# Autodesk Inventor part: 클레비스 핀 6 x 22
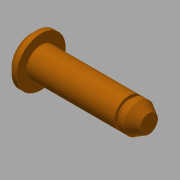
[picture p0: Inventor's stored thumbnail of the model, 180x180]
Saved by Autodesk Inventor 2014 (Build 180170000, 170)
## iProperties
IsCustomPart: 1
Created: 2017-08
Part Number: 클레비스 핀 6 x 22
Material: 강철
Description: 머리가 있는 클레비스 핀
Document SubType Name: Modeling
Standard: ISO 2341
Designer: mduedu
Standard Revision: Second edition 1986-11-01
Standards Organization: ISO
Language: ko-KR
Size Designation: B - 6 x 24
Categories: <MemberInstance><Categories><Category DisplayName="조임쇠" InternalName="e4da775c-781d-43d5-af7c-5136215cf5a6" Mnemonic="FSTN"><Category DisplayName="핀" InternalNa
Density: 7.85 g/cm^3
Appearance: Orange
Author: mduedu
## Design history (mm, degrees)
sketch "스케치1"
  geometry: L1 (-2, 0)-(-2, 5); L2 (-2, 5)-(0, 5); L3 (0, 5)-(0, 3); L4 (0, 3)-(22, 3); L5 (22, 3)-(22, 0); L6 (-2, 0)-(22, 0); L7 (-7, 0)-(28, 0) reference; L8 (0, -1.96)-(0, 6.16) reference; C1 r 0.8 at (18.8, 0)
  constraints: 12 end point, 3 parallel, 2 collinear, 2 perpendicular, 1 centre point, 1 point on line, 1 vertical
  dimensions: "d0" = 6 diameter of L4 L6 (= NND); "d1" = 10 diameter of L2 L6 (= KOD); "d2" = 2 distance of L1.end L2.end (= KOH); "d3" = 22 distance of L3.end L4.end (= NLG); "d5" = 3.2 distance from line of L5 C1.centre (= DIST); "d6" = 1.6 diameter of C1 (= BOR)
revolve "본체" stored, may be unused: angle "d4" = 90 deg
node "작업 평면4"
sketch "스케치2"
  geometry: C1 r 3 at (0, 0) reference; C2 r 2.425 at (0, 0); 1 further point
  constraints: 1 centre point, 1 coincident
  dimensions: "d33" = 4.85 diameter of C2
extrude "돌출2" cut sketch "스케치2" distance "d34" = 0.7; taper "d35" = 0 deg
body "Solid1"
chamfer "모따기1" distance "d9" = 1 (= PHH2); stored, may be unused: angle "d10" = 45 deg (= FAWI2), second distance "d16" = 1 (= PHH2)
chamfer "모따기2" distance "d11" = 2 (= PHH1); stored, may be unused: angle "d12" = 30 deg (= FAWI1), second distance "d17" = 2 (= PHH1)
workplane "Work Plane1"
other parameters: "PHH1" = 2 [user parameter; used in 2 equation terms], "PHH2" = 1 [user parameter; used in 2 equation terms], "KOD" = 10 [user parameter; used in 1 equation term], "KOH" = 2 [user parameter; used in 1 equation term], "NND" = 6 [user parameter; used in 1 equation term], "FAWI1" = 30 deg [user parameter; used in 1 equation term], "FAWI2" = 45 deg [user parameter; used in 1 equation term], "DIST" = 3.2 [user parameter; used in 1 equation term], "BOR" = 1.6 [user parameter; used in 1 equation term], "NLG" = 22 [user parameter; used in 1 equation term], "d13" = 0, "d14" = 0, "d30" = 0, "d32" = 18
